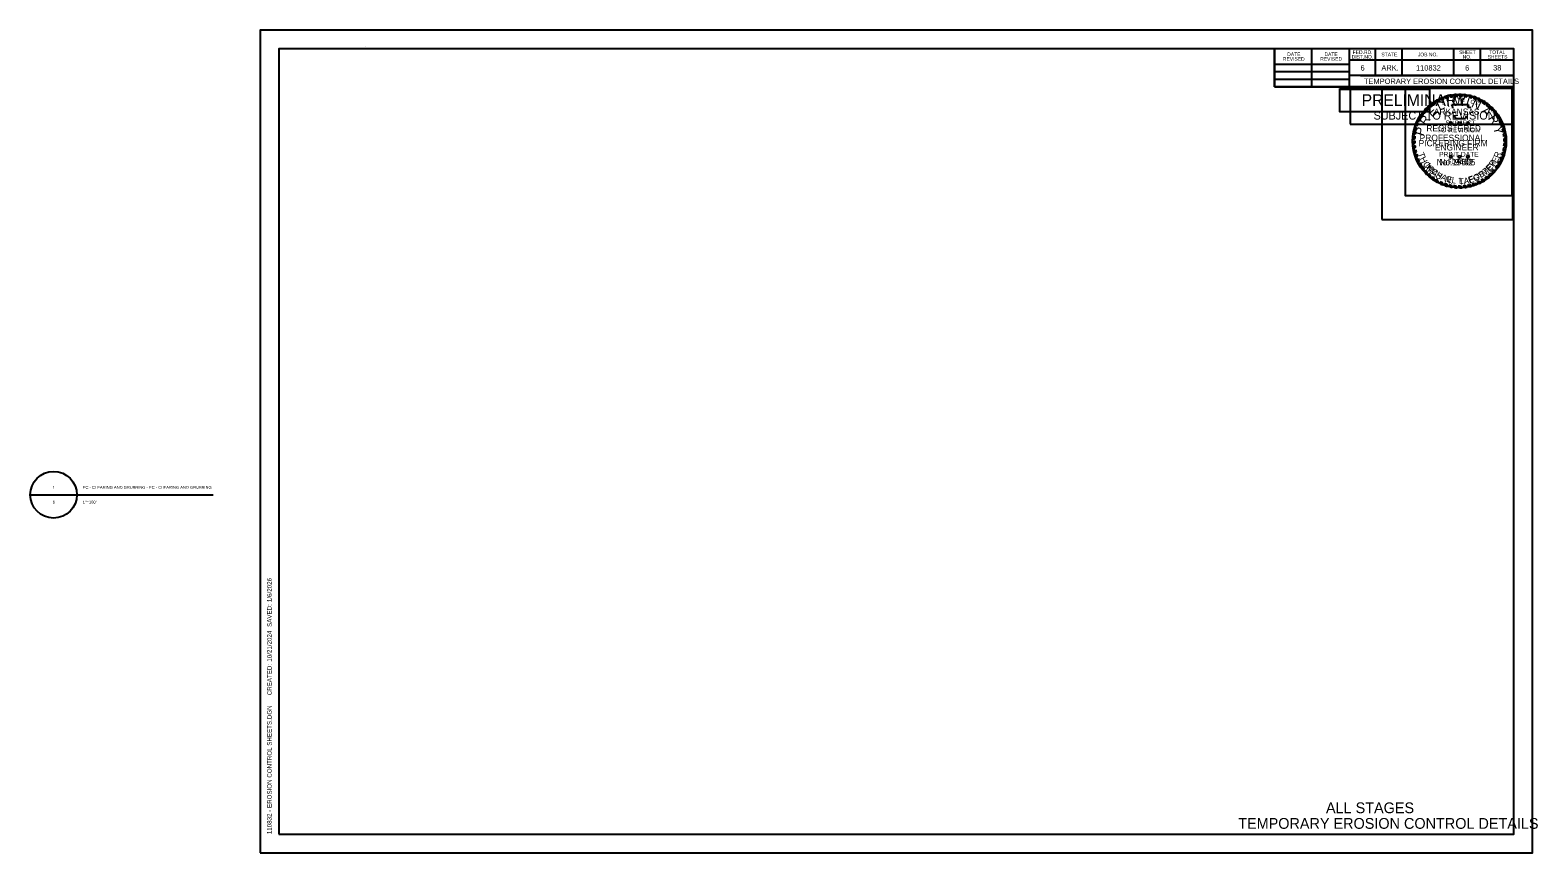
# Model space of a CAD drawing. Extents: x -0.26 to 1.42, y 0 to 0.92.
import ezdxf

# ---------------------------------------------------------------- set-up
doc = ezdxf.new("R2010")
doc.units = 0
for name, color, linetype in [('_CG Flow Arrow', 7, 'Continuous'), ('_PROJECT LIMITS', 7, 'Continuous'), ('_REM', 7, 'Continuous'), ('_SILT FENCE_CG', 7, 'Continuous'), ('DSN_DRFT_Guideline-No-Plot', 7, 'Continuous'), ('Legend', 7, 'Continuous'), ('R_Border Notes', 7, 'Continuous'), ('S_BUILDING', 7, 'Continuous'), ('S_GAS_UTILITIES', 7, 'Continuous'), ('S_PHOTO_CTL_ANNOT', 7, 'Continuous'), ('SHET_Border-Lines', 7, 'Continuous'), ('SHET_Stamp-Prelim', 7, 'Continuous'), ('SHET_Stamp-Seal', 7, 'Continuous')]:
    doc.layers.add(name, color=color, linetype=linetype)

msp = doc.modelspace()

# ---------------------------------------------------------------- linework, layer by layer
at = {"layer": 'DSN_DRFT_Guideline-No-Plot'}
msp.add_lwpolyline([(0, 0), (1.4167, 0), (1.4167, 0.9167), (0, 0.9167)], close=True, dxfattribs=at)
at = {"layer": 'Legend'}
msp.add_lwpolyline([(1.2022, 0.8508), (1.3022, 0.8508), (1.3022, 0.8258), (1.2022, 0.8258)], close=True, dxfattribs=at)
at = {"layer": 'R_Border Notes'}
for p, q in [((0.1176, 0.8988), (0.1176, 0.8988)), ((0.1176, 0.8988), (0.1176, 0.8988)), ((1.1296, 0.8534), (1.1296, 0.8958)), ((1.1711, 0.8534), (1.1711, 0.8958)), ((1.2127, 0.8958), (1.2127, 0.8534)), ((1.2417, 0.8958), (1.2417, 0.866)), ((1.2712, 0.8958), (1.2712, 0.866)), ((1.3289, 0.8958), (1.3289, 0.866)), ((1.3584, 0.8958), (1.3584, 0.866)), ((1.1296, 0.8786), (1.2127, 0.8786)), ((1.3958, 0.8832), (1.2127, 0.8832)), ((1.3958, 0.8833), (1.3958, 0.8833)), ((1.1296, 0.8706), (1.2127, 0.8706)), ((1.1296, 0.8622), (1.2127, 0.8622)), ((1.3958, 0.866), (1.2127, 0.866)), ((1.2252, 0.866), (1.3958, 0.866)), ((1.3958, 0.8534), (1.1296, 0.8534))]:
    msp.add_line(p, q, dxfattribs=at)
for points in [[(0.0208, 0.0208), (1.3958, 0.0208), (1.3958, 0.8958), (0.0208, 0.8958)], [(1.1296, 0.8534), (1.3958, 0.8534), (1.3958, 0.8958), (1.1296, 0.8958)]]:
    msp.add_lwpolyline(points, close=True, dxfattribs=at)
at = {"layer": 'S_BUILDING'}
msp.add_line((1.3219, 0.7895), (1.3219, 0.7895), dxfattribs=at)
msp.add_lwpolyline([(1.249, 0.7057), (1.3948, 0.7057), (1.3948, 0.8524), (1.249, 0.8524)], close=True, dxfattribs=at)
at = {"layer": 'S_GAS_UTILITIES'}
msp.add_lwpolyline([(1.2137, 0.8119), (1.3948, 0.8119), (1.3948, 0.8524), (1.2137, 0.8524)], close=True, dxfattribs=at)
at = {"layer": 'S_PHOTO_CTL_ANNOT'}
for p, q in [((1.3137, 0.8403), (1.3158, 0.8387)), ((1.3165, 0.8415), (1.3181, 0.8397)), ((1.3184, 0.8422), (1.3206, 0.8405)), ((1.3217, 0.8432), (1.3233, 0.8413)), ((1.3239, 0.8438), (1.3259, 0.8418)), ((1.3266, 0.8443), (1.3283, 0.8422)), ((1.3295, 0.8447), (1.331, 0.8426)), ((1.3336, 0.8427), (1.3318, 0.8449)), ((1.3364, 0.8428), (1.3348, 0.845)), ((1.3389, 0.8426), (1.3375, 0.845)), ((1.3417, 0.8424), (1.3401, 0.8448)), ((1.3441, 0.842), (1.3427, 0.8445)), ((1.3473, 0.8413), (1.3463, 0.8439)), ((1.3495, 0.8407), (1.3486, 0.8433)), ((1.352, 0.8399), (1.3512, 0.8426)), ((1.3544, 0.839), (1.3536, 0.8418)), ((1.357, 0.8379), (1.3564, 0.8406)), ((1.3594, 0.8366), (1.359, 0.8394)), ((1.293, 0.8232), (1.2959, 0.8232)), ((1.2946, 0.8253), (1.2977, 0.8254)), ((1.2965, 0.8276), (1.2994, 0.8274)), ((1.2983, 0.8295), (1.3014, 0.8293)), ((1.3002, 0.8313), (1.3028, 0.8306)), ((1.3021, 0.833), (1.3051, 0.8325)), ((1.3042, 0.8348), (1.3068, 0.8337)), ((1.3066, 0.8363), (1.309, 0.8352)), ((1.3087, 0.8377), (1.3112, 0.8365)), ((1.3112, 0.8391), (1.3138, 0.8378)), ((1.3269, 0.8337), (1.3456, 0.8337)), ((1.3276, 0.832), (1.3269, 0.8337)), ((1.3281, 0.8303), (1.3276, 0.832)), ((1.3282, 0.8297), (1.3281, 0.8303)), ((1.3456, 0.8337), (1.3443, 0.831)), ((1.3443, 0.831), (1.3478, 0.831)), ((1.3478, 0.831), (1.347, 0.8297)), ((1.3616, 0.8353), (1.3614, 0.8381)), ((1.364, 0.8337), (1.3639, 0.8366)), ((1.366, 0.8322), (1.3662, 0.8349)), ((1.3685, 0.8301), (1.3687, 0.8331)), ((1.3703, 0.8285), (1.3707, 0.8313)), ((1.3723, 0.8264), (1.3727, 0.8294)), ((1.3738, 0.8247), (1.3746, 0.8273)), ((1.3756, 0.8223), (1.3764, 0.8251)), ((1.3769, 0.8206), (1.3779, 0.8232)), ((1.2847, 0.8048), (1.2873, 0.8059)), ((1.2853, 0.8071), (1.2879, 0.808)), ((1.2862, 0.8099), (1.2889, 0.8106)), ((1.287, 0.8121), (1.2898, 0.8129)), ((1.288, 0.8145), (1.2908, 0.8151)), ((1.2891, 0.8167), (1.2918, 0.8171)), ((1.2904, 0.8191), (1.2931, 0.8192)), ((1.2917, 0.8213), (1.2946, 0.8215)), ((1.3252, 0.8129), (1.3241, 0.8137)), ((1.3241, 0.8137), (1.3255, 0.8137)), ((1.3248, 0.8116), (1.3252, 0.8129)), ((1.3259, 0.8124), (1.3248, 0.8116)), ((1.3255, 0.8137), (1.3259, 0.815)), ((1.3259, 0.815), (1.3264, 0.8137)), ((1.327, 0.8116), (1.3259, 0.8124)), ((1.3264, 0.8137), (1.3277, 0.8137)), ((1.3277, 0.8137), (1.3266, 0.8129)), ((1.3266, 0.8129), (1.327, 0.8116)), ((1.3293, 0.8201), (1.3291, 0.8213)), ((1.331, 0.8201), (1.3293, 0.8201)), ((1.331, 0.8177), (1.331, 0.8201)), ((1.3423, 0.8177), (1.331, 0.8177)), ((1.3347, 0.8129), (1.3336, 0.8137)), ((1.3336, 0.8137), (1.335, 0.8137)), ((1.3343, 0.8116), (1.3347, 0.8129)), ((1.3354, 0.8124), (1.3343, 0.8116)), ((1.335, 0.8137), (1.3354, 0.815)), ((1.3354, 0.815), (1.3358, 0.8137)), ((1.3365, 0.8116), (1.3354, 0.8124)), ((1.3358, 0.8137), (1.3372, 0.8137)), ((1.3372, 0.8137), (1.3361, 0.8129)), ((1.3361, 0.8129), (1.3365, 0.8116)), ((1.3424, 0.8196), (1.3423, 0.8177)), ((1.3429, 0.8213), (1.3424, 0.8196)), ((1.3442, 0.8129), (1.3431, 0.8137)), ((1.3431, 0.8137), (1.3445, 0.8137)), ((1.3438, 0.8116), (1.3442, 0.8129)), ((1.3449, 0.8124), (1.3438, 0.8116)), ((1.3445, 0.8137), (1.3449, 0.815)), ((1.3449, 0.815), (1.3453, 0.8137)), ((1.346, 0.8116), (1.3449, 0.8124)), ((1.3453, 0.8137), (1.3467, 0.8137)), ((1.3467, 0.8137), (1.3456, 0.8129)), ((1.3456, 0.8129), (1.346, 0.8116)), ((1.3786, 0.8178), (1.3796, 0.8205)), ((1.3797, 0.8157), (1.381, 0.8182)), ((1.381, 0.813), (1.3823, 0.8157)), ((1.3818, 0.8112), (1.3832, 0.8136)), ((1.3829, 0.8081), (1.3844, 0.8107)), ((1.3835, 0.8061), (1.3851, 0.8086)), ((1.2857, 0.796), (1.2834, 0.7946)), ((1.2856, 0.7933), (1.2834, 0.7914)), ((1.2859, 0.7984), (1.2835, 0.7968)), ((1.2857, 0.791), (1.2835, 0.7892)), ((1.2862, 0.8008), (1.2838, 0.7996)), ((1.2867, 0.8034), (1.2841, 0.802)), ((1.3842, 0.8029), (1.386, 0.8054)), ((1.3846, 0.8008), (1.3866, 0.8028)), ((1.3849, 0.7876), (1.3874, 0.7891)), ((1.385, 0.798), (1.387, 0.7998)), ((1.3851, 0.7956), (1.3873, 0.7973)), ((1.3852, 0.7927), (1.3875, 0.7945)), ((1.3852, 0.7905), (1.3875, 0.792)), ((1.2858, 0.7882), (1.2838, 0.7862)), ((1.2861, 0.7858), (1.2842, 0.7837)), ((1.2866, 0.7833), (1.2847, 0.7812)), ((1.2871, 0.7809), (1.2854, 0.7786)), ((1.2878, 0.7784), (1.2861, 0.7761)), ((1.2886, 0.7761), (1.287, 0.7738)), ((1.2895, 0.7737), (1.288, 0.7713)), ((1.3252, 0.7754), (1.3241, 0.7763)), ((1.3241, 0.7763), (1.3255, 0.7763)), ((1.3248, 0.7741), (1.3252, 0.7754)), ((1.3259, 0.7749), (1.3248, 0.7741)), ((1.3255, 0.7763), (1.3259, 0.7776)), ((1.3259, 0.7776), (1.3264, 0.7763)), ((1.327, 0.7741), (1.3259, 0.7749)), ((1.3264, 0.7763), (1.3277, 0.7763)), ((1.3277, 0.7763), (1.3266, 0.7754)), ((1.3266, 0.7754), (1.327, 0.7741)), ((1.3347, 0.7754), (1.3336, 0.7763)), ((1.3336, 0.7763), (1.335, 0.7763)), ((1.3343, 0.7741), (1.3347, 0.7754)), ((1.3354, 0.7749), (1.3343, 0.7741)), ((1.335, 0.7763), (1.3354, 0.7776)), ((1.3354, 0.7776), (1.3358, 0.7763)), ((1.3365, 0.7741), (1.3354, 0.7749)), ((1.3358, 0.7763), (1.3372, 0.7763)), ((1.3372, 0.7763), (1.3361, 0.7754)), ((1.3361, 0.7754), (1.3365, 0.7741)), ((1.3442, 0.7754), (1.3431, 0.7763)), ((1.3431, 0.7763), (1.3445, 0.7763)), ((1.3438, 0.7741), (1.3442, 0.7754)), ((1.3449, 0.7749), (1.3438, 0.7741)), ((1.3445, 0.7763), (1.3449, 0.7776)), ((1.3449, 0.7776), (1.3453, 0.7763)), ((1.346, 0.7741), (1.3449, 0.7749)), ((1.3453, 0.7763), (1.3467, 0.7763)), ((1.3467, 0.7763), (1.3456, 0.7754)), ((1.3456, 0.7754), (1.346, 0.7741)), ((1.3808, 0.7724), (1.3835, 0.7729)), ((1.382, 0.7753), (1.3847, 0.776)), ((1.3827, 0.7774), (1.3855, 0.7785)), ((1.3835, 0.7802), (1.3862, 0.7813)), ((1.3841, 0.7827), (1.3867, 0.7838)), ((1.3846, 0.7855), (1.3871, 0.7867)), ((1.2905, 0.7715), (1.2892, 0.769)), ((1.2918, 0.769), (1.2907, 0.7662)), ((1.2931, 0.7667), (1.2921, 0.7641)), ((1.2942, 0.765), (1.2936, 0.7619)), ((1.2958, 0.7628), (1.2952, 0.7598)), ((1.2975, 0.7607), (1.297, 0.7578)), ((1.2992, 0.7588), (1.2988, 0.7559)), ((1.301, 0.757), (1.3008, 0.754)), ((1.3702, 0.7573), (1.3727, 0.7566)), ((1.3716, 0.7588), (1.3743, 0.7583)), ((1.3738, 0.7612), (1.3763, 0.7608)), ((1.3755, 0.7634), (1.3783, 0.7634)), ((1.3774, 0.7662), (1.3801, 0.7661)), ((1.3783, 0.7677), (1.3811, 0.768)), ((1.3799, 0.7705), (1.3826, 0.7709)), ((1.3029, 0.7552), (1.3029, 0.7523)), ((1.3049, 0.7536), (1.305, 0.7507)), ((1.3068, 0.7522), (1.307, 0.7493)), ((1.3092, 0.7506), (1.3095, 0.7478)), ((1.3111, 0.7495), (1.3117, 0.7466)), ((1.3138, 0.7481), (1.3147, 0.7452)), ((1.3159, 0.7471), (1.3169, 0.7443)), ((1.3187, 0.7461), (1.3198, 0.7433)), ((1.321, 0.7453), (1.3222, 0.7426)), ((1.3238, 0.7445), (1.325, 0.7419)), ((1.326, 0.7441), (1.3274, 0.7415)), ((1.3288, 0.7436), (1.3302, 0.7411)), ((1.3313, 0.7433), (1.3328, 0.7409)), ((1.334, 0.7432), (1.3356, 0.7409)), ((1.3365, 0.7432), (1.3384, 0.741)), ((1.3394, 0.7433), (1.3412, 0.7412)), ((1.3419, 0.7436), (1.344, 0.7416)), ((1.3444, 0.744), (1.3465, 0.7421)), ((1.3471, 0.7446), (1.3492, 0.7427)), ((1.3497, 0.7453), (1.352, 0.7436)), ((1.3524, 0.7462), (1.3549, 0.7447)), ((1.3548, 0.7471), (1.3571, 0.7456)), ((1.3573, 0.7483), (1.36, 0.7471)), ((1.3596, 0.7494), (1.3619, 0.7481)), ((1.3619, 0.7508), (1.3644, 0.7497)), ((1.3639, 0.7521), (1.3663, 0.751)), ((1.3664, 0.754), (1.369, 0.7532)), ((1.3679, 0.7553), (1.3706, 0.7545))]:
    msp.add_line(p, q, dxfattribs=at)
for radius, start, end in [(0.0521, 111.3124, 114.7026), (0.0498, 110.3086, 113.1659), (0.0521, 105.2339, 109.0352), (0.0498, 104.0352, 107.3615), (0.0521, 99.7525, 102.7765), (0.0498, 98.258, 101.0329), (0.0521, 93.9381, 96.5517), (0.0498, 92.1102, 95.0367), (0.0521, 87.7298, 90.6707), (0.0498, 85.9628, 88.9097), (0.0521, 81.9732, 84.8236), (0.0498, 79.9264, 82.696), (0.0521, 75.3125, 77.9426), (0.0498, 73.5575, 76.2314), (0.0521, 69.6061, 72.3058), (0.0498, 67.6248, 70.504), (0.0521, 63.1329, 66.2704), (0.0521, 141.6056, 144.4486), (0.0498, 139.301, 142.5873), (0.0521, 135.4021, 138.3031), (0.0498, 133.1331, 136.2562), (0.0521, 129.7326, 132.5376), (0.0498, 127.5297, 130.9683), (0.0521, 123.6199, 126.5906), (0.0498, 121.9746, 125.11), (0.0521, 117.6544, 120.8099), (0.0498, 115.6869, 119.1583), (0.0498, 61.1558, 64.3784), (0.0521, 56.9003, 60.0942), (0.0498, 54.9238, 58.2702), (0.0498, 48.3016, 52.0395), (0.0521, 50.3492, 53.7159), (0.0498, 42.2212, 45.5512), (0.0521, 44.3405, 47.3929), (0.0498, 36.135, 39.5311), (0.0521, 38.1247, 41.2316), (0.0521, 31.9614, 35.4294), (0.0521, 164.3068, 166.894), (0.0521, 158.4077, 161.0701), (0.0498, 162.4331, 165.0013), (0.0521, 152.864, 155.5189), (0.0498, 156.3402, 159.2319), (0.0521, 147.0072, 149.899), (0.0498, 151.0315, 153.573), (0.0498, 145.0197, 148.2104), (0.0498, 29.9032, 33.6645), (0.0498, 23.7732, 27.2211), (0.0521, 25.9391, 29.0125), (0.0498, 17.6802, 21.4251), (0.0521, 19.9538, 23.3141), (0.0498, 11.5444, 15.2364), (0.0521, 13.8421, 17.4447), (0.0521, 175.7409, 178.2066), (0.0521, 181.7251, 184.1626), (0.0521, 170.0003, 172.6878), (0.0498, 179.6454, 182.2633), (0.0498, 173.73, 176.4734), (0.0498, 167.9048, 170.9039), (0.0498, 5.7599, 9.0606), (0.0498, 353.8632, 357.1274), (0.0498, 359.7329, 3.0639), (0.0521, 7.5852, 10.8621), (0.0521, 1.7215, 4.7268), (0.0521, 355.7156, 358.9569), (0.0521, 187.4204, 190.1927), (0.0521, 193.0369, 195.9973), (0.0498, 185.4539, 188.234), (0.0521, 198.8967, 201.6281), (0.0498, 191.2274, 193.9858), (0.0498, 196.9675, 199.8353), (0.0498, 202.7761, 205.4791), (0.0498, 335.6038, 339.1858), (0.0498, 341.777, 345.0925), (0.0521, 337.3837, 340.9933), (0.0498, 348.0778, 351.3435), (0.0521, 343.8925, 347.035), (0.0521, 349.8305, 353.0885), (0.0521, 204.5479, 207.4328), (0.0521, 210.8636, 213.6571), (0.0498, 208.7883, 211.7934), (0.0521, 216.6115, 219.491), (0.0498, 214.1838, 217.2747), (0.0521, 222.48, 225.3801), (0.0498, 220.3909, 223.3056), (0.0498, 226.2494, 229.2407), (0.0498, 310.7744, 314.3161), (0.0521, 312.4518, 315.6633), (0.0498, 316.6531, 320.3711), (0.0521, 318.2846, 321.8043), (0.0498, 323.5851, 327.4407), (0.0498, 329.5549, 333.2076), (0.0521, 325.4405, 328.9872), (0.0521, 331.4037, 334.9332), (0.0521, 228.3665, 231.348), (0.0498, 232.229, 234.9336), (0.0521, 234.295, 236.9452), (0.0498, 238.2223, 240.8353), (0.0521, 240.1977, 242.8613), (0.0498, 244.3204, 246.9486), (0.0521, 246.576, 249.1558), (0.0498, 250.3491, 253.1216), (0.0521, 252.5967, 255.3252), (0.0498, 256.505, 259.1192), (0.0521, 258.4433, 261.1398), (0.0498, 262.3783, 265.2012), (0.0521, 264.1978, 267.1009), (0.0498, 268.3215, 271.277), (0.0521, 270.2548, 273.3361), (0.0498, 274.6157, 277.4486), (0.0521, 276.4239, 279.4357), (0.0498, 280.3459, 283.5814), (0.0521, 282.3199, 285.3702), (0.0498, 286.6423, 289.9783), (0.0521, 288.5709, 291.9733), (0.0498, 292.8745, 296.1185), (0.0521, 294.6481, 298.2166), (0.0498, 299.0768, 302.1724), (0.0521, 300.621, 303.8703), (0.0498, 304.823, 308.5143), (0.0521, 306.3721, 310.208)]:
    msp.add_arc((1.3354, 0.793), radius, start, end, dxfattribs=at)
at = {"layer": 'SHET_Border-Lines'}
for p, q in [((-0.256, 0.399), (-0.2039, 0.399)), ((-0.2297, 0.399), (-0.0521, 0.399))]:
    msp.add_line(p, q, dxfattribs=at)
msp.add_circle((-0.2299, 0.399), 0.026, dxfattribs=at)
at = {"layer": 'SHET_Stamp-Prelim'}
msp.add_circle((1.3354, 0.793), 0.0521, dxfattribs=at)
at = {"layer": 'SHET_Stamp-Seal'}
for points in [[(1.2022, 0.8517), (1.3022, 0.8517), (1.3022, 0.8258), (1.2022, 0.8258)], [(1.3942, 0.8517), (1.275, 0.8517), (1.275, 0.7325), (1.3942, 0.7325)]]:
    msp.add_lwpolyline(points, close=True, dxfattribs=at)

# ---------------------------------------------------------------- texts
at = {"layer": '_CG Flow Arrow'}
for s, height, p in [('6', 0.006, (1.2252, 0.8716)), ('ARK.', 0.006, (1.2485, 0.8716)), ('110832', 0.006, (1.287, 0.8716)), ('6', 0.006, (1.3417, 0.8716)), ('38', 0.006, (1.3729, 0.8717)), ('TEMPORARY EROSION CONTROL DETAILS', 0.006, (1.2291, 0.8567)), ('ALL STAGES', 0.012, (1.1868, 0.0442)), ('TEMPORARY EROSION CONTROL DETAILS', 0.012, (1.0891, 0.0268))]:
    msp.add_text(s, height=height, dxfattribs=at).set_placement(p)
at = {"layer": '_PROJECT LIMITS'}
for s, rotation, p in [('T', 289.646, (1.289, 0.7791)), ('H', 296.7339, (1.291, 0.7736)), ('E', 63.0984, (1.377, 0.768)), ('R', 69.57, (1.3798, 0.7735)), ('O', 303.7708, (1.2943, 0.7674)), ('M', 314.2033, (1.298, 0.7621)), ('A', 321.0594, (1.3034, 0.7567)), ('S', 327.8239, (1.308, 0.7531)), ('G', 23.3052, (1.3522, 0.7475)), ('T', 31.466, (1.3583, 0.7503)), ('M', 39.3, (1.3633, 0.7533)), ('E', 46.8094, (1.3692, 0.7582)), ('Y', 53.9986, (1.3733, 0.7628)), ('N', 344.2727, (1.3186, 0.7474)), ('.', 350.6464, (1.3254, 0.7456)), ('T', 3.0061, (1.3347, 0.7445)), ('A', 8.9826, (1.3405, 0.7448)), ('E', 17.6836, (1.3463, 0.7457))]:
    msp.add_text(s, height=0.00698, rotation=rotation, dxfattribs=at).set_placement(p)
msp.add_text('No. 19605', height=0.00698, dxfattribs=at).set_placement((1.3101, 0.7661))
at = {"layer": '_REM'}
for s, p in [('DATE', (1.1436, 0.8878)), ('DATE', (1.1851, 0.8878)), ('FED.RD.', (1.2165, 0.8901)), ('STATE', (1.2485, 0.8875)), ('JOB NO.', (1.2891, 0.8875)), ('SHEET', (1.335, 0.8901)), ('TOTAL', (1.3686, 0.8901)), ('REVISED', (1.1388, 0.8826)), ('REVISED', (1.1804, 0.8826)), ('DIST.NO.', (1.2154, 0.8849)), ('NO.', (1.339, 0.8849)), ('SHEETS', (1.3668, 0.8849))]:
    msp.add_text(s, height=0.004, dxfattribs=at).set_placement(p)
for s, p in [('1/6/2026', (0.0129, 0.2794)), ('  SAVED: ', (0.0129, 0.2479)), ('10/21/2024', (0.0129, 0.213)), ('     CREATED: ', (0.0129, 0.166)), ('110832 - EROSION CONTROL SHEETS.DGN', (0.0129, 0.0208))]:
    msp.add_text(s, height=0.005, rotation=90, dxfattribs=at).set_placement(p)
at = {"layer": '_SILT FENCE_CG'}
msp.add_text('No. 9402', height=0.00698, dxfattribs=at).set_placement((1.313, 0.7661))
for s, rotation, p in [('M', 308.339, (1.297, 0.7652)), ('I', 314.1842, (1.3014, 0.7599)), ('C', 319.8733, (1.3034, 0.7579)), ('H', 327.7235, (1.3086, 0.7538)), ('A', 335.7276, (1.3141, 0.7506)), ('O', 23.719, (1.3526, 0.7487)), ('S', 31.7234, (1.3588, 0.7517)), ('T', 39.4194, (1.3641, 0.7552)), ('E', 46.9613, (1.3689, 0.7594)), ('R', 54.5031, (1.373, 0.764)), ('E', 343.5779, (1.3204, 0.748)), ('L', 350.8115, (1.3263, 0.7464)), ('L', 1.2666, (1.3349, 0.7455)), ('.', 6.8035, (1.3408, 0.7459)), ('F', 15.8691, (1.3468, 0.7469))]:
    msp.add_text(s, height=0.0067, rotation=rotation, dxfattribs=at).set_placement(p)
at = {"layer": 'S_GAS_UTILITIES'}
for s, height, p in [('PRELIMINARY', 0.013, (1.2266, 0.8322)), ('SUBJECT TO REVISION', 0.009, (1.2398, 0.817))]:
    msp.add_text(s, height=height, dxfattribs=at).set_placement(p)
at = {"layer": 'S_PHOTO_CTL_ANNOT'}
for s, rotation, p in [('T', 16.311, (1.3216, 0.8347)), ('A', 9.0679, (1.3269, 0.8361)), ('T', 1.8248, (1.3325, 0.8369)), ('E', 355.2002, (1.3375, 0.8369)), ('S', 23.5541, (1.3164, 0.8327)), ('O', 342.2506, (1.3472, 0.8354)), ('F', 335.0075, (1.3526, 0.8335))]:
    msp.add_text(s, height=0.00436, rotation=rotation, dxfattribs=at).set_placement(p)
for s, height, p in [('ARKANSAS', 0.00698, (1.3069, 0.8223)), ('REGISTERED', 0.00698, (1.2986, 0.8038)), ('PROFESSIONAL', 0.006983, (1.2911, 0.7932)), ('ENGINEER', 0.00698, (1.3081, 0.7826))]:
    msp.add_text(s, height=height, dxfattribs=at).set_placement(p)
at = {"layer": 'SHET_Border-Lines'}
for s, height, p in [('1', 0.00328, (-0.2308, 0.4056)), ('EC - CLEARING AND GRUBBING - EC - CLEARING AND GRUBBING', 0.003281, (-0.1974, 0.4056)), ('6', 0.00328, (-0.2309, 0.3892)), ('1"=100\'', 0.00328, (-0.1974, 0.3892))]:
    msp.add_text(s, height=height, dxfattribs=at).set_placement(p)
at = {"layer": 'SHET_Stamp-Prelim'}
for s, rotation, p in [('I', 12.5248, (1.3217, 0.8309)), ('M', 3.1074, (1.3278, 0.8326)), ('I', 342.3164, (1.3416, 0.833)), ('N', 333.9382, (1.3478, 0.8315)), ('E', 42.3578, (1.3048, 0.8192)), ('L', 25.513, (1.3131, 0.8266)), ('A', 315.6579, (1.3591, 0.8257)), ('R', 301.3831, (1.3668, 0.8184)), ('P', 73.913, (1.2953, 0.7982)), ('R', 56.2292, (1.2984, 0.8095)), ('Y', 283.2593, (1.3729, 0.8084))]:
    msp.add_text(s, height=0.0101, rotation=rotation, dxfattribs=at).set_placement(p)
for s, height, p in [('TO REVISION', 0.005363, (1.3105, 0.8028)), ('SUBJECT', 0.00536, (1.3198, 0.8106)), ('PICKERING FIRM', 0.006983, (1.29, 0.7872)), ('PRINT DATE', 0.00536, (1.3128, 0.7757)), ('$DATE$', 0.00536, (1.3222, 0.768))]:
    msp.add_text(s, height=height, dxfattribs=at).set_placement(p)

doc.saveas('drawing.dxf')
